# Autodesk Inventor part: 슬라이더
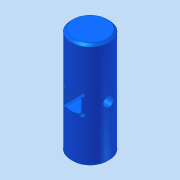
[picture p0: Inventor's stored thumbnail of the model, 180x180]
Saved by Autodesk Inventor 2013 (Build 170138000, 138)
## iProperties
Company: 한국ATC센터
Created: 2015-04
Part Number: 슬라이더
Document SubType Name: Modeling
Designer: KYOUNG IL JANG
Density: 7.85 g/cm^3
Material: 강철
Mass: 88.0136 g
Surface Area: 38.892 cm^2
Volume: 11.2119 cm^3
Author: KYOUNG IL JANG
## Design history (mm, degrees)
sketch "스케치1"
  geometry: C1 r 9 at (0, 0); 1 further point
  constraints: 1 centre point, 1 coincident
  dimensions: "d0" = 18 diameter of C1
extrude "돌출1" new body sketch "스케치1" stored distance "d1" = 50; taper "d2" = 0 deg
node "작업 평면1"
sketch "스케치3"
  geometry: L1 (4, 25)-(-4, 25); L2 (-4, 25)-(-4, -25); L3 (-4, -25)-(4, -25); L4 (4, -25)-(4, 25); 3 further points
  constraints: 8 end point, 2 midpoint, 2 parallel, 1 horizontal, 1 horizontal alignment, 1 perpendicular, 1 vertical alignment
  dimensions: "d5" = 8 distance of L1.start L1.end; "d6" = 50 distance of L1.end L2.end
extrude "돌출3" cut sketch "스케치3" stored distance "d7" = 8; taper "d8" = 0 deg
sketch "스케치4"
  geometry: 5 further points
hole "구멍1" sketch "스케치4" at (4, 4), (-4, 4), (-4, -4), (4, -4) diameter "d9" = 2; stored, may be unused: countersink angle "d13" = 90 deg, drill point angle "d15" = 118 deg; dims "d10" = 6, "d11" = 4, "d12" = 2, "d14" = 8
node "작업 평면2"
sketch "스케치5"
  geometry: 1 further point
hole "구멍2" sketch "스케치5" at (0, 0) diameter "d16" = 5; stored, may be unused: countersink angle "d20" = 90 deg, drill point angle "d22" = 118 deg; dims "d17" = 6, "d18" = 4, "d19" = 2, "d21" = 8
chamfer "모따기1" distance "d23" = 1; stored, may be unused: second distance "d24" = 2, angle "d25" = 45 deg
node "솔리드1"
mirror "대칭1"
